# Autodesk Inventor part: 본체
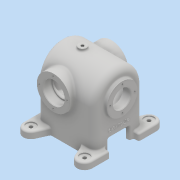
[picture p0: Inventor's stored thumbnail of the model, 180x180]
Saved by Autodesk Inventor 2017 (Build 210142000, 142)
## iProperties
Part Number: 본체
Material: 일반
Document SubType Name: Modeling
Designer: MRC
Density: 1 g/cm^3
Appearance: 기본값
Author: MRC
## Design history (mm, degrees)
sketch "스케치1"
  geometry: L1 (0, 45)-(0, 45); L2 (45, 0)-(45, -80); L3 (45, -80)-(-45, -80); L4 (-45, -80)-(-45, 0); L5 (-20, -57)-(20, -57); L6 (20, -57)-(20, -80); L7 (20, -80)-(-20, -80); L8 (-20, -80)-(-20, -57); A1 r 45 centre (0, 0) between (0, 45) and (-45, 0); A2 r 45 centre (0, 0) between (45, 0) and (0, 45); 2 further points
  constraints: 16 end point, 4 parallel, 4 point on circle, 4 tangent, 2 centre point, 2 horizontal, 2 horizontal alignment, 2 perpendicular, 2 point on line, 1 concentric
  dimensions: "d0" = 90 distance of L2.end L3.end; "d1" = 125 distance of point (45, 45) L2.end; "d2" = 45 radius of A1; "d3" = 45 distance from line of point (0, 0) L2; "d4" = 40 distance of L5.start L5.end; "d5" = 23 distance of L5.end L6.end; "d6" = 20 distance from line of L8 point (0, 0)
extrude "돌출1" new body sketch "스케치1" stored distance "d7" = 108; taper "d8" = 0 deg
sketch "스케치4"
  geometry: L1 (-54, -80)-(-54, 0) reference; L2 (54, 0)-(54, -80) reference; C1 r 31 at (14, 0); 1 further point
  constraints: 1 centre point, 1 horizontal alignment
  dimensions: "d12" = 62 diameter of C1; "d14" = 40 distance from line of C1.centre L2
extrude "돌출3" join sketch "스케치4" stored distance "d15" = 108; taper "d16" = 0 deg
sketch "스케치5"
  geometry: C1 r 28.5 at (0, 0); 1 further point
  constraints: 1 centre point, 1 coincident
  dimensions: "d17" = 57 diameter of C1
extrude "돌출4" join sketch "스케치5" distance "d18" = 6; taper "d19" = 0 deg
node "작업 평면1"
sketch "스케치6"
  geometry: L1 (60, -28.5)-(60, 28.5) reference; C1 r 7.5 at (-14, 0); 1 further point
  constraints: 1 centre point, 1 horizontal alignment
  dimensions: "d21" = 15 diameter of C1; "d22" = 74 distance from line of C1.centre L1
extrude "돌출5" join sketch "스케치6" stored distance "d23" = 6; taper "d24" = 0 deg
sketch "스케치7"
  geometry: L1 (45, 33)-(45, 0); L2 (45, 0)-(-60, 0); L3 (-60, 0)-(-60, 16.5); L4 (-60, 16.5)-(-45, 16.5); L5 (-45, 16.5)-(-45, 33); L6 (-42, 36)-(42, 36); L7 (-60, 28.5)-(-60, -28.5) reference; A1 r 3 centre (-42, 33) between (-42, 36) and (-45, 33); A2 r 3 centre (42, 33) between (45, 33) and (42, 36); 3 further points
  constraints: 12 end point, 4 horizontal alignment, 4 perpendicular, 4 point on circle, 4 point on line, 4 tangent, 2 centre point, 1 equal radius, 1 horizontal, 1 vertical
  dimensions: "d25" = 16.5 distance of L2.end L3.end; "d26" = 105 distance of L1.end L2.end; "d27" = 36 distance of point (45, 36) L1.end; "d28" = 90 distance of point (-45, 36) point (45, 36); "d29" = 0 distance between parallel lines of L3 L7; "d30" = 3 radius of A1
revolve "회전1" sketch "스케치7" stored, may be unused: angle "d31" = 90 deg
sketch "스케치9"
  geometry: L1 (-36, -80)-(36, -80); L2 (36, -80)-(36, -27); L3 (-36, -27)-(-36, -80); L4 (45, -80)-(20, -80) reference; L5 (45, 0)-(45, -80) reference; L6 (-45, -80)-(-45, 0) reference; A1 r 45 centre (0, 0) between (-36, -27) and (45, 0); 1 further point
  constraints: 6 end point, 3 point on circle, 1 centre point, 1 coincident, 1 horizontal, 1 parallel, 1 perpendicular, 1 point on line
  dimensions: "d38" = 90 diameter of A1; "d39" = 0 distance between parallel lines of L4 L1; "d40" = 9 distance between parallel lines of L5 L2; "d41" = 9 distance between parallel lines of L3 L6
extrude "돌출6" cut sketch "스케치9" stored distance "d42" = 90; taper "d43" = 0 deg
hole "구멍1" diameter "d46" = 5.188; stored, may be unused: countersink angle "d50" = 90 deg, drill point angle "d52" = 118 deg; dims "d44" = 10, "d45" = 10, "d47" = 12, "d48" = 4, "d49" = 2, "d51" = 100
hole "구멍2" diameter "d62" = 35; stored, may be unused: countersink angle "d66" = 90 deg, drill point angle "d68" = 118 deg; dims "d60" = 10, "d61" = 10, "d63" = 12, "d64" = 40, "d65" = 16, "d67" = 50
hole "구멍3" diameter "d71" = 35; stored, may be unused: countersink angle "d75" = 90 deg, drill point angle "d77" = 118 deg; dims "d69" = 10, "d70" = 10, "d72" = 12, "d73" = 40, "d74" = 16, "d76" = 50
sketch "스케치11"
  geometry: L1 (0, 0)-(-23, 0)
  constraints: 2 end point, 1 horizontal
  dimensions: "d78" = 23 distance of L1.start L1.end
hole "구멍4" sketch "스케치11" at (-23, 0) diameter "d79" = 3.242; stored, may be unused: countersink angle "d83" = 90 deg, drill point angle "d85" = 118 deg; dims "d80" = 8, "d81" = 40, "d82" = 16, "d84" = 10
sketch "스케치12"
  geometry: L1 (0, 0)-(-26, 0); C1 r 17.5 at (0, 0) reference; 1 further point
  constraints: 2 end point, 1 horizontal
  dimensions: "d89" = 26 distance of L1.start L1.end
hole "구멍5" sketch "스케치12" at (-26, 0) diameter "d90" = 3.242; stored, may be unused: countersink angle "d94" = 90 deg, drill point angle "d96" = 118 deg; dims "d91" = 8, "d92" = 40, "d93" = 16, "d95" = 10
sketch "스케치13"
  geometry: L1 (57, -20)-(57, 20) reference; L2 (80, 20)-(80, 45) reference; 2 further points
  constraints: 1 horizontal alignment, 1 other
  dimensions: "d101" = 35 distance from line of point (45, 0) L2
feature "엠보싱1" sketch "스케치13" dims "d0" = 90, "d1" = 125, "d2" = 45, "d3" = 45, "d4" = 40, "d5" = 23, "d6" = 20, "d102" = 0.5, "d103" = 0
sketch "스케치16"
  geometry: L1 (99, 25)-(99, 9) reference; L2 (99, 9)-(9, 9) reference; L3 (9, 9)-(9, 25) reference; L4 (9, 25)-(0, 25) reference; L5 (0, 0)-(0, 25) reference; L6 (108, 0)-(0, 0) reference; L7 (108, 25)-(108, 0) reference; L8 (108, 25)-(99, 25) reference; L9 (99, 81)-(99, 65) reference; L10 (99, 65)-(108, 65) reference; L11 (108, 90)-(108, 65) reference; L12 (0, 90)-(108, 90) reference; L13 (0, 65)-(0, 90) reference; L14 (0, 65)-(9, 65) reference; L15 (9, 65)-(9, 81) reference; L16 (9, 81)-(99, 81) reference; L17 (91.21, -20.693)-(82, 0); L18 (108, 0)-(0, 0) reference; L19 (108, 18)-(118, 18); L20 (118, 18)-(118, -15); L21 (54, 45)-(33.69, 45); L22 (54, 45)-(54, 29.29); L23 (108, 72)-(118, 72); L24 (118, 72)-(118, 105); L25 (91.21, 110.693)-(82, 90); L26 (16.79, -20.693)-(26, 0); L27 (-10, 18)-(-10, -15); L28 (0, 18)-(-10, 18); L29 (-10, 72)-(-10, 105); L30 (0, 72)-(-10, 72); L31 (16.79, 110.693)-(26, 90); L32 (108, 72)-(108, 90); L33 (108, 90)-(82, 90); L34 (26, 90)-(0, 90); L35 (0, 90)-(0, 72); L36 (0, 18)-(0, 0); L37 (26, 0)-(0, 0); L38 (82, 0)-(108, 0); L39 (108, 18)-(108, 0); A1 r 14 centre (104, -15) between (91.21, -20.693) and (118, -15); A2 r 14 centre (104, 105) between (118, 105) and (91.21, 110.693); A3 r 14 centre (4, -15) between (-10, -15) and (16.79, -20.693); A4 r 14 centre (4, 105) between (16.79, 110.693) and (-10, 105)
  constraints: 44 end point, 18 symmetric about line, 8 point on circle, 7 collinear, 4 centre point, 4 point on line, 2 horizontal, 2 perpendicular, 2 tangent, 1 horizontal alignment, 1 vertical, 3 other
  dimensions: "d111" = 18 distance between parallel lines of L6 L19; "d112" = 28 diameter of A1; "d113" = 60 vertical distance of L20.end L21.start; "d114" = 36 distance from line of L17.end L20; "d115" = 64 distance from line of L20 L21.start; "d116" = 4.29025 distance from line of L22.end L8; "d117" = 74.30956 distance from line of L21.end L7
extrude "돌출7" join sketch "스케치16" distance "d118" = 12; taper "d119" = 0 deg
hole "구멍6" diameter "d122" = 6.6; stored, may be unused: countersink angle "d126" = 90 deg, drill point angle "d128" = 118 deg; dims "d120" = 10, "d121" = 10, "d123" = 8, "d124" = 18, "d125" = 2, "d127" = 10
hole "구멍7" diameter "d131" = 6.6; stored, may be unused: countersink angle "d135" = 90 deg, drill point angle "d137" = 118 deg; dims "d129" = 10, "d130" = 10, "d132" = 8, "d133" = 18, "d134" = 2, "d136" = 10
hole "구멍8" diameter "d140" = 6.6; stored, may be unused: countersink angle "d144" = 90 deg, drill point angle "d146" = 118 deg; dims "d138" = 10, "d139" = 10, "d141" = 8, "d142" = 18, "d143" = 2, "d145" = 10
hole "구멍9" diameter "d149" = 6.6; stored, may be unused: countersink angle "d153" = 90 deg, drill point angle "d155" = 118 deg; dims "d147" = 10, "d148" = 10, "d150" = 8, "d151" = 18, "d152" = 2, "d154" = 10
chamfer "모따기1" distance "d156" = 1; stored, may be unused: second distance "d157" = 2, angle "d158" = 45 deg
fillet "모깎기1" dims "d159" = 0.3
fillet "모깎기2" dims "d160" = 3
fillet "모깎기3" dims "d161" = 12
fillet "모깎기4" dims "d162" = 3
fillet "모깎기5" dims "d163" = 3
fillet "모깎기6" dims "d164" = 3
fillet "모깎기7" dims "d165" = 3
node "솔리드1"
mirror "미러1"
pattern_circular "원형 패턴1" dims angle "d87" = 360 deg
pattern_circular "원형 패턴2" dims angle "d98" = 360 deg
mirror "미러2"
node "투영된 루프3"
node "투영된 루프4"
other parameters: "d20" = 49
